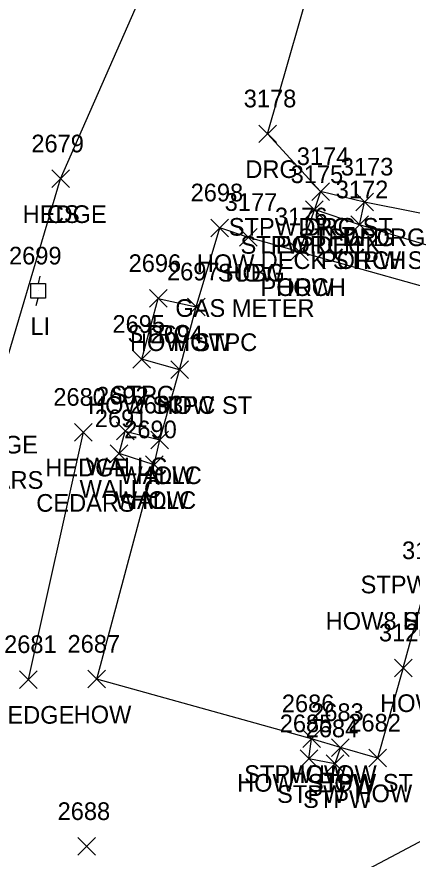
# Model space of a CAD drawing. Extents: x 1477930 to 1480780, y 774090 to 784647.
# Drawn here: x 1479474.7 to 1479519.5, y 774762.5 to 774857.9 of the extents above; entities that cross this region are included whole.
import ezdxf

# ---------------------------------------------------------------- set-up
doc = ezdxf.new("R2010")
doc.units = 0
for name, color, linetype in [('L_A', 7, 'Continuous'), ('L_C', 7, 'Continuous'), ('L_I', 7, 'Continuous'), ('L_TIC', 7, 'Continuous'), ('LAHR', 7, 'Continuous'), ('LBC', 7, 'Continuous'), ('LBF', 7, 'Continuous'), ('LELB', 7, 'Continuous'), ('LW', 7, 'Continuous'), ('R_A', 7, 'Continuous'), ('R_I', 7, 'Continuous'), ('R_TIC', 7, 'Continuous'), ('RDG', 7, 'Continuous'), ('RSW', 7, 'Continuous'), ('U_A', 7, 'Continuous'), ('U_C', 7, 'Continuous'), ('U_I', 7, 'Continuous'), ('U_TIC', 7, 'Continuous'), ('ULP', 7, 'Continuous')]:
    doc.layers.add(name, color=color, linetype=linetype)

msp = doc.modelspace()

# ---------------------------------------------------------------- linework, layer by layer
at = {"layer": 'L_TIC'}
for points in [[(1479478.663, 774838.548), (1479480.663, 774840.548)], [(1479480.663, 774838.548), (1479478.663, 774840.548)], [(1479478.663, 774838.548), (1479480.663, 774840.548)], [(1479480.663, 774838.548), (1479478.663, 774840.548)], [(1479508.084, 774837.108), (1479510.084, 774839.108)], [(1479510.084, 774837.108), (1479508.084, 774839.108)], [(1479513.065, 774835.924), (1479515.065, 774837.924)], [(1479515.065, 774835.924), (1479513.065, 774837.924)], [(1479507.389, 774835.064), (1479509.389, 774837.064)], [(1479509.389, 774835.064), (1479507.389, 774837.064)], [(1479507.389, 774835.064), (1479509.389, 774837.064)], [(1479509.389, 774835.064), (1479507.389, 774837.064)], [(1479496.683, 774832.996), (1479498.683, 774834.996)], [(1479498.683, 774832.996), (1479496.683, 774834.996)], [(1479512.492, 774833.341), (1479514.492, 774835.341)], [(1479514.492, 774833.341), (1479512.492, 774835.341)], [(1479512.492, 774833.341), (1479514.492, 774835.341)], [(1479514.492, 774833.341), (1479512.492, 774835.341)], [(1479499.925, 774831.917), (1479501.925, 774833.917)], [(1479501.925, 774831.917), (1479499.925, 774833.917)], [(1479505.67, 774830.282), (1479507.67, 774832.282)], [(1479507.67, 774830.282), (1479505.67, 774832.282)], [(1479505.67, 774830.282), (1479507.67, 774832.282)], [(1479507.67, 774830.282), (1479505.67, 774832.282)], [(1479489.72, 774824.999), (1479491.72, 774826.999)], [(1479491.72, 774824.999), (1479489.72, 774826.999)], [(1479494.012, 774824.047), (1479496.012, 774826.047)], [(1479496.012, 774824.047), (1479494.012, 774826.047)], [(1479494.012, 774824.047), (1479496.012, 774826.047)], [(1479496.012, 774824.047), (1479494.012, 774826.047)], [(1479487.838, 774818.111), (1479489.838, 774820.111)], [(1479489.838, 774818.111), (1479487.838, 774820.111)], [(1479492.136, 774816.925), (1479494.136, 774818.925)], [(1479494.136, 774816.925), (1479492.136, 774818.925)], [(1479492.136, 774816.925), (1479494.136, 774818.925)], [(1479494.136, 774816.925), (1479492.136, 774818.925)], [(1479481.23, 774809.848), (1479483.23, 774811.848)], [(1479483.23, 774809.848), (1479481.23, 774811.848)], [(1479485.984, 774809.987), (1479487.984, 774811.987)], [(1479487.984, 774809.987), (1479485.984, 774811.987)], [(1479489.886, 774808.978), (1479491.886, 774810.978)], [(1479491.886, 774808.978), (1479489.886, 774810.978)], [(1479489.886, 774808.978), (1479491.886, 774810.978)], [(1479491.886, 774808.978), (1479489.886, 774810.978)], [(1479485.273, 774807.432), (1479487.273, 774809.432)], [(1479487.273, 774807.432), (1479485.273, 774809.432)], [(1479489.256, 774806.167), (1479491.256, 774808.167)], [(1479491.256, 774806.167), (1479489.256, 774808.167)], [(1479489.256, 774806.167), (1479491.256, 774808.167)], [(1479491.256, 774806.167), (1479489.256, 774808.167)], [(1479517.439, 774783.168), (1479519.439, 774785.168)], [(1479519.439, 774783.168), (1479517.439, 774785.168)], [(1479475.005, 774781.845), (1479477.005, 774783.845)], [(1479477.005, 774781.845), (1479475.005, 774783.845)], [(1479482.751, 774781.89), (1479484.751, 774783.89)], [(1479484.751, 774781.89), (1479482.751, 774783.89)], [(1479507.062, 774775.14), (1479509.062, 774777.14)], [(1479509.062, 774775.14), (1479507.062, 774777.14)], [(1479507.062, 774775.14), (1479509.062, 774777.14)], [(1479509.062, 774775.14), (1479507.062, 774777.14)], [(1479510.325, 774774.147), (1479512.325, 774776.147)], [(1479512.325, 774774.147), (1479510.325, 774776.147)], [(1479510.325, 774774.147), (1479512.325, 774776.147)], [(1479512.325, 774774.147), (1479510.325, 774776.147)], [(1479506.772, 774772.879), (1479508.772, 774774.879)], [(1479508.772, 774772.879), (1479506.772, 774774.879)], [(1479514.534, 774772.955), (1479516.534, 774774.955)], [(1479516.534, 774772.955), (1479514.534, 774774.955)], [(1479514.534, 774772.955), (1479516.534, 774774.955)], [(1479516.534, 774772.955), (1479514.534, 774774.955)], [(1479509.707, 774772.306), (1479511.707, 774774.306)], [(1479511.707, 774772.306), (1479509.707, 774774.306)], [(1479481.629, 774762.938), (1479483.629, 774764.938)], [(1479483.629, 774762.938), (1479481.629, 774764.938)]]:
    msp.add_lwpolyline(points, dxfattribs=at)
at = {"layer": 'LAHR'}
for points in [[(1479471.887, 774813.444), (1479479.663, 774839.548)], [(1479482.23, 774810.848), (1479476.005, 774782.845)]]:
    msp.add_lwpolyline(points, dxfattribs=at)
at = {"layer": 'LBC'}
for points in [[(1479515.534, 774773.955), (1479511.325, 774775.147), (1479508.062, 774776.14), (1479483.751, 774782.89), (1479490.256, 774807.167), (1479490.886, 774809.978), (1479493.136, 774817.925), (1479495.012, 774825.047), (1479497.683, 774833.996)], [(1479500.925, 774832.917), (1479497.683, 774833.996)], [(1479518.439, 774784.168), (1479521, 774793.48), (1479522.131, 774797.607), (1479523.767, 774803.55), (1479530.448, 774801.304), (1479533.175, 774811.235), (1479536.326, 774822.874), (1479534.918, 774823.368), (1479506.67, 774831.282), (1479500.925, 774832.917)], [(1479518.439, 774784.168), (1479515.534, 774773.955)]]:
    msp.add_lwpolyline(points, dxfattribs=at)
at = {"layer": 'LBF'}
for points in [[(1479513.492, 774834.341), (1479514.065, 774836.924), (1479509.084, 774838.108), (1479508.389, 774836.064)], [(1479534.918, 774823.368), (1479535.871, 774827.584), (1479513.492, 774834.341), (1479508.389, 774836.064), (1479506.67, 774831.282)], [(1479493.136, 774817.925), (1479488.838, 774819.111), (1479490.72, 774825.999), (1479495.012, 774825.047)], [(1479511.325, 774775.147), (1479510.707, 774773.306), (1479507.772, 774773.879), (1479508.062, 774776.14)]]:
    msp.add_lwpolyline(points, dxfattribs=at)
at = {"layer": 'LELB'}
msp.add_lwpolyline([(1479479.663, 774839.548), (1479495.288, 774875.166), (1479490.05, 774880.629), (1479497.692, 774904.015), (1479504.171, 774926.128), (1479523.996, 774969.758), (1479529.795, 774996.905)], dxfattribs=at)
at = {"layer": 'LW'}
msp.add_lwpolyline([(1479490.256, 774807.167), (1479486.273, 774808.432), (1479486.984, 774810.987), (1479490.886, 774809.978)], dxfattribs=at)
at = {"layer": 'R_TIC'}
for points in [[(1479502.08, 774843.644), (1479504.08, 774845.644)], [(1479504.08, 774843.644), (1479502.08, 774845.644)], [(1479508.084, 774837.108), (1479510.084, 774839.108)], [(1479510.084, 774837.108), (1479508.084, 774839.108)], [(1479513.065, 774835.924), (1479515.065, 774837.924)], [(1479515.065, 774835.924), (1479513.065, 774837.924)]]:
    msp.add_lwpolyline(points, dxfattribs=at)
at = {"layer": 'RDG'}
for points in [[(1479509.084, 774838.108), (1479503.08, 774844.644), (1479515.086, 774886.506), (1479523.786, 774914.637), (1479529.027, 774933.272), (1479538.693, 774931.369)], [(1479598.757, 774810.291), (1479588.804, 774826.084), (1479565.978, 774842.708), (1479549.849, 774844.203), (1479543.643, 774826.727), (1479535.871, 774827.584), (1479537.401, 774832.244), (1479514.065, 774836.924)]]:
    msp.add_lwpolyline(points, dxfattribs=at)
at = {"layer": 'RSW'}
msp.add_lwpolyline([(1479454.048, 774732.201), (1479457.362, 774735.507), (1479461.547, 774734.407), (1479499.972, 774753.705), (1479531.618, 774770.459), (1479545.779, 774777.94), (1479596.697, 774804.864), (1479626.336, 774821.051), (1479665.838, 774842.34), (1479709.717, 774866.291), (1479748.232, 774887.235), (1479790.979, 774910.551), (1479825.884, 774929.42), (1479857.892, 774946.347), (1479880.805, 774958.363), (1479898.018, 774967.807), (1479932.308, 774985.558), (1479966.418, 775003.673), (1480005.027, 775023.737)], dxfattribs=at)
at = {"layer": 'U_TIC'}
for points in [[(1479499.925, 774831.917), (1479501.925, 774833.917)], [(1479501.925, 774831.917), (1479499.925, 774833.917)]]:
    msp.add_lwpolyline(points, dxfattribs=at)
at = {"layer": 'ULP'}
for p, q in [((1479477.303, 774828.519), (1479477.137, 774827.686)), ((1479476.303, 774826.019), (1479476.303, 774827.686)), ((1479476.303, 774827.686), (1479477.97, 774827.686)), ((1479477.97, 774827.686), (1479477.97, 774826.019)), ((1479477.97, 774826.019), (1479476.303, 774826.019)), ((1479476.887, 774825.186), (1479477.137, 774826.019)), ((1479477.137, 774826.853), (1479477.137, 774826.853))]:
    msp.add_line(p, q, dxfattribs=at)

# ---------------------------------------------------------------- texts
at = {"layer": 'L_A'}
for s, p in [('HEDGE', (1479475.364, 774834.548)), ('CS', (1479478.104, 774834.548)), ('STPW DRG ST', (1479498.698, 774833.108)), ('STPW DRG', (1479506.546, 774831.924)), ('STPW DECK', (1479500.027, 774831.064)), ('PORCH', (1479504.011, 774831.064)), ('HOW', (1479495.069, 774828.996)), ('DECK STPW ST', (1479502.303, 774829.341)), ('PORCH', (1479509.115, 774829.341)), ('HOW', (1479498.311, 774827.917)), ('PORCH', (1479502.292, 774826.282)), ('HOW', (1479504.056, 774826.282)), ('STPC', (1479487.232, 774820.999)), ('HOW STPC', (1479487.508, 774820.047)), ('HOW', (1479492.398, 774820.047)), ('STPC', (1479485.35, 774814.111)), ('HOW STPC ST', (1479482.766, 774812.925)), ('HOW', (1479490.522, 774812.925)), ('HEDGE', (1479467.588, 774808.444)), ('HEDGE', (1479477.931, 774805.848)), ('WALLC', (1479482.519, 774805.987)), ('WALLC', (1479486.422, 774804.978)), ('HOW', (1479488.272, 774804.978)), ('WALLC', (1479481.809, 774803.432)), ('WALLC', (1479485.791, 774802.167)), ('HOW', (1479487.641, 774802.167)), ('STPW HOW8', (1479513.612, 774792.607)), ('HOW8 STPW ST', (1479509.654, 774788.48)), ('HOW', (1479518.386, 774788.48)), ('HOW', (1479515.825, 774779.168)), ('HEDGE', (1479471.706, 774777.845)), ('HOW', (1479481.137, 774777.89)), ('STPW HOW', (1479500.44, 774771.14)), ('HOW', (1479505.448, 774771.14)), ('HOW  STPW ST', (1479499.632, 774770.147)), ('HOW', (1479508.711, 774770.147)), ('STPW', (1479504.166, 774768.879)), ('HOW', (1479512.92, 774768.955)), ('HOW', (1479512.92, 774768.955)), ('STPW', (1479507.101, 774768.306))]:
    msp.add_text(s, height=2, dxfattribs=at).set_placement(p)
at = {"layer": 'L_C'}
for p in [(1479466.564, 774804.444), (1479476.907, 774801.848)]:
    msp.add_text('CEDARS', height=2, dxfattribs=at).set_placement(p)
at = {"layer": 'L_I'}
for s, p in [('2679', (1479476.348, 774842.548)), ('2679', (1479476.348, 774842.548)), ('3174', (1479506.391, 774841.108)), ('3173', (1479511.372, 774839.924)), ('3175', (1479505.696, 774839.064)), ('3175', (1479505.696, 774839.064)), ('3172', (1479510.8, 774837.341)), ('3172', (1479510.8, 774837.341)), ('2698', (1479494.376, 774836.996)), ('3177', (1479498.232, 774835.917)), ('3176', (1479503.922, 774834.282)), ('3176', (1479503.922, 774834.282)), ('2696', (1479487.358, 774828.999)), ('2697', (1479491.705, 774828.047)), ('2697', (1479491.705, 774828.047)), ('2695', (1479485.531, 774822.111)), ('2694', (1479489.829, 774820.925)), ('2694', (1479489.829, 774820.925)), ('2680', (1479478.836, 774813.848)), ('2692', (1479483.677, 774813.987)), ('2693', (1479487.579, 774812.978)), ('2693', (1479487.579, 774812.978)), ('2691', (1479483.533, 774811.432)), ('2690', (1479486.862, 774810.167)), ('2690', (1479486.862, 774810.167)), ('3127', (1479518.307, 774796.48)), ('3127', (1479518.307, 774796.48)), ('3126', (1479515.691, 774787.168)), ('2681', (1479473.265, 774785.845)), ('2687', (1479480.444, 774785.89)), ('2686', (1479504.7, 774779.14)), ('2686', (1479504.7, 774779.14)), ('2683', (1479508.018, 774778.147)), ('2683', (1479508.018, 774778.147)), ('2685', (1479504.465, 774776.879)), ('2684', (1479507.4, 774776.306)), ('2682', (1479512.227, 774776.955)), ('2682', (1479512.227, 774776.955)), ('2688', (1479479.322, 774766.938))]:
    msp.add_text(s, height=2, dxfattribs=at).set_placement(p)
at = {"layer": 'R_A'}
for p in [(1479500.569, 774839.644), (1479506.572, 774833.108), (1479511.554, 774831.924)]:
    msp.add_text('DRG', height=2, dxfattribs=at).set_placement(p)
at = {"layer": 'R_I'}
for s, p in [('3178', (1479500.388, 774847.644)), ('3174', (1479506.391, 774841.108)), ('3173', (1479511.372, 774839.924))]:
    msp.add_text(s, height=2, dxfattribs=at).set_placement(p)
at = {"layer": 'U_A'}
for s, p in [('SUBG', (1479497.453, 774827.917)), ('LI', (1479476.239, 774821.853))]:
    msp.add_text(s, height=2, dxfattribs=at).set_placement(p)
at = {"layer": 'U_C'}
msp.add_text('GAS METER', height=2, dxfattribs=at).set_placement((1479492.649, 774823.917))
at = {"layer": 'U_I'}
for s, p in [('3177', (1479498.232, 774835.917)), ('2699', (1479473.822, 774829.853))]:
    msp.add_text(s, height=2, dxfattribs=at).set_placement(p)

doc.saveas('drawing.dxf')
